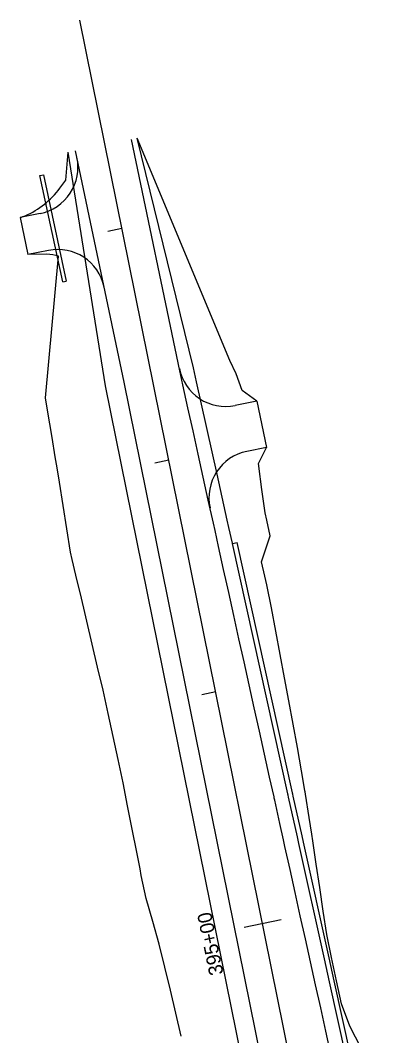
# Model space of a CAD drawing. Extents: x 948761 to 996004, y 1858548 to 1925175.
# Drawn here: x 960010 to 960167.1, y 1910227.2 to 1910656.8 of the extents above; entities that cross this region are included whole.
import ezdxf

# ---------------------------------------------------------------- set-up
doc = ezdxf.new("R2010")
doc.units = 0
for name, color, linetype in [('R_Drainage', 7, 'Continuous'), ('R_Horz Alg', 7, 'Continuous'), ('R_Horz Alg Annot', 7, 'Continuous'), ('R_Proposed Const Limits', 7, 'Continuous'), ('R_Proposed Road', 7, 'Continuous')]:
    doc.layers.add(name, color=color, linetype=linetype)

msp = doc.modelspace()

# ---------------------------------------------------------------- linework, layer by layer
at = {"layer": 'R_Drainage'}
for p, q in [((960018.29, 1910591.14), (960019.78, 1910591.46)), ((960019.78, 1910591.46), (960029.45, 1910546.49)), ((960027.96, 1910546.17), (960018.29, 1910591.14)), ((960027.96, 1910546.17), (960029.45, 1910546.49))]:
    msp.add_line(p, q, dxfattribs=at)
at = {"layer": 'R_Horz Alg'}
msp.add_line((960128.14, 1910197.39), (960035.16, 1910656.78), dxfattribs=at)
at = {"layer": 'R_Horz Alg Annot'}
for points in [[(960047.09, 1910567.6), (960052.97, 1910568.79)], [(960066.92, 1910469.59), (960072.8, 1910470.78)], [(960086.76, 1910371.57), (960092.64, 1910372.76)], [(960104.64, 1910273.16), (960120.32, 1910276.34)]]:
    msp.add_lwpolyline(points, dxfattribs=at)
at = {"layer": 'R_Proposed Const Limits'}
msp.add_line((960021.25, 1910557.91), (960013.17, 1910557.67), dxfattribs=at)
for points in [[(960110.06, 1910495.66), (960103.89, 1910500.12), (960101.29, 1910507.15), (960098.56, 1910512.79), (960059.43, 1910606.9)], [(960029.21, 1910589.21), (960030.31, 1910601)], [(960026.76, 1910585.75), (960029.21, 1910589.21)], [(960078.08, 1910226.98), (960075.83, 1910236.73), (960073.56, 1910246.47), (960071.2, 1910256.19), (960068.67, 1910265.88), (960066, 1910275.55), (960063.24, 1910285.19), (960061.16, 1910294.97), (960060.66, 1910297.76), (960059.24, 1910304.79), (960057.32, 1910314.6), (960057.05, 1910316.03), (960055.37, 1910324.41), (960053.45, 1910334.22), (960051.37, 1910344.01), (960049.31, 1910353.79), (960047.21, 1910363.57), (960045.02, 1910373.33), (960042.66, 1910383.05), (960040.45, 1910392.81), (960038.13, 1910402.54), (960037.31, 1910406.21), (960035.84, 1910412.28), (960033.55, 1910422.02), (960031.99, 1910428.68), (960031.24, 1910431.76), (960029.71, 1910441.65), (960028.18, 1910451.46), (960028.17, 1910451.54), (960026.59, 1910461.42), (960025.43, 1910468.33), (960024.93, 1910471.29), (960023.3, 1910481.16), (960021.64, 1910491.03), (960020.63, 1910497.02), (960026.22, 1910557.06)], [(960115.66, 1910438.64), (960114.27, 1910445.34), (960113.62, 1910448.43), (960112.23, 1910458.35), (960110.85, 1910468.19), (960110.84, 1910468.27), (960110.71, 1910469.22), (960114.12, 1910476.08)], [(960149.46, 1910231.22), (960145.92, 1910240.71), (960143.75, 1910250.47), (960141.59, 1910260.24), (960139.62, 1910270.04), (960138.14, 1910279.95), (960136.67, 1910289.85), (960135.16, 1910299.75), (960133.69, 1910309.65), (960133.26, 1910312.45), (960132.16, 1910319.54), (960130.62, 1910329.44), (960130.47, 1910330.34), (960130.4, 1910330.73), (960130.38, 1910330.87), (960128.93, 1910339.3), (960127.26, 1910349.16), (960125.44, 1910359), (960123.6, 1910368.83), (960121.76, 1910378.66), (960119.91, 1910388.49), (960118.08, 1910398.32), (960116.24, 1910408.15), (960114.22, 1910417.94), (960113.38, 1910421.61), (960111.96, 1910427.69), (960115.66, 1910438.64)], [(960167.1, 1910184.41), (960163.72, 1910193.62), (960160.48, 1910202.88), (960157.44, 1910212.43), (960154.13, 1910221.96), (960149.46, 1910231.22)]]:
    msp.add_lwpolyline(points, dxfattribs=at)
for centre, major_axis, ratio, start_param, end_param in [((959996.98, 1910608.16), (25.78, 26.92), 0.999994, 4.322581, 4.831192), ((959986.48, 1910645.12), (72.74, 24.01), 0.98582, 4.710332, 4.739066), ((960014.59, 1910503.91), (-49.71, 22.13), 0.999787, 4.915808, 5.008467)]:
    msp.add_ellipse(centre, major_axis=major_axis, ratio=ratio, start_param=start_param, end_param=end_param, dxfattribs=at)
at = {"layer": 'R_Proposed Road'}
for p, q in [((960077.41, 1910508.51), (960057.06, 1910606.42)), ((960083.29, 1910509.7), (960059.43, 1910606.9)), ((960046.05, 1910502.16), (960030.31, 1910601)), ((960053.89, 1910503.75), (960033.36, 1910601.62)), ((960018.35, 1910575.05), (960010, 1910573.36)), ((960010, 1910573.36), (960013.17, 1910557.67)), ((960021.91, 1910559.44), (960013.17, 1910557.67)), ((960108.53, 1910193.43), (960046.05, 1910502.16)), ((960116.37, 1910195.01), (960053.89, 1910503.75)), ((960110.06, 1910495.66), (960100.85, 1910493.8)), ((960110.06, 1910495.66), (960114.12, 1910476.08)), ((960114.12, 1910476.08), (960105.82, 1910474.4)), ((960099.74, 1910435.42), (960101.7, 1910435.81))]:
    msp.add_line(p, q, dxfattribs=at)
for points in [[(960099.74, 1910435.42), (960099.71, 1910435.52), (960098.24, 1910442.2), (960097.55, 1910445.29), (960095.39, 1910455.05), (960093.25, 1910464.73), (960093.23, 1910464.81), (960084.58, 1910503.88), (960083.27, 1910509.81)], [(960141.42, 1910219.39), (960139.26, 1910229.16), (960137.09, 1910238.92), (960134.93, 1910248.69), (960132.77, 1910258.45), (960130.61, 1910268.22), (960128.45, 1910277.98), (960126.29, 1910287.75), (960124.12, 1910297.51), (960121.96, 1910307.28), (960121.35, 1910310.04), (960119.8, 1910317.04), (960117.64, 1910326.81), (960117.44, 1910327.7), (960117.35, 1910328.09), (960117.32, 1910328.23), (960115.47, 1910336.57), (960113.31, 1910346.34), (960111.15, 1910356.1), (960108.99, 1910365.87), (960106.83, 1910375.64), (960104.67, 1910385.4), (960102.5, 1910395.17), (960100.34, 1910404.93), (960098.18, 1910414.7), (960097.37, 1910418.37), (960096.02, 1910424.46), (960093.85, 1910434.23), (960092.38, 1910440.91), (960091.69, 1910443.99), (960089.53, 1910453.76), (960087.39, 1910463.44), (960087.37, 1910463.52), (960085.21, 1910473.29), (960083.05, 1910483.05), (960080.88, 1910492.82), (960078.72, 1910502.58), (960077.41, 1910508.51)], [(960151.37, 1910202.21), (960140.79, 1910249.98), (960138.63, 1910259.75), (960127.82, 1910308.58), (960127.21, 1910311.34), (960123.5, 1910328.11), (960123.3, 1910329), (960123.21, 1910329.39), (960123.18, 1910329.52), (960099.74, 1910435.42)], [(960153.32, 1910202.64), (960142.74, 1910250.42), (960140.58, 1910260.18), (960129.77, 1910309.01), (960129.16, 1910311.77), (960125.45, 1910328.54), (960125.25, 1910329.44), (960125.16, 1910329.83), (960125.13, 1910329.96), (960101.69, 1910435.85)]]:
    msp.add_lwpolyline(points, dxfattribs=at)
for centre, start, end in [((960014.38, 1910594.65), 281.4419, 11.8462), ((960025.88, 1910539.84), 11.8462, 101.4419), ((960096.88, 1910513.4), 191.423, 281.4419), ((960109.79, 1910454.8), 101.4419, 192.4785)]:
    msp.add_arc(centre, 20, start, end, dxfattribs=at)

# ---------------------------------------------------------------- texts
at = {"layer": 'R_Horz Alg Annot'}
msp.add_text('395+00', height=6, rotation=101.4419, dxfattribs=at).set_placement((960095.98, 1910253.41))

doc.saveas('drawing.dxf')
